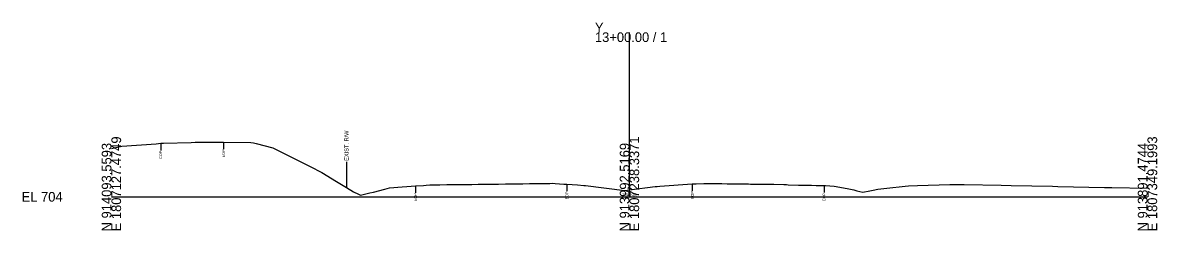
# Model space of a CAD drawing. Extents: x -26 to 3303, y -30 to 9580.
# Drawn here: x -25.7 to 302.8, y 2990.3 to 3050.4 of the extents above; entities that cross this region are included whole.
import ezdxf

# ---------------------------------------------------------------- set-up
doc = ezdxf.new("R2010")
doc.units = 0
for name, color, linetype in [('Exist Cross Section Cell', 7, 'Continuous'), ('Exist XS Center Line Elevation Label', 7, 'Continuous'), ('Exist XS Ground Line', 7, 'Continuous'), ('Old_Level_10', 7, 'Continuous')]:
    doc.layers.add(name, color=color, linetype=linetype)

msp = doc.modelspace()

# ---------------------------------------------------------------- linework, layer by layer
at = {"layer": 'Exist Cross Section Cell'}
for p, q in [((150, 3000), (150, 3047.62)), ((0, 3000), (150, 3000)), ((150, 3000), (300, 3000))]:
    msp.add_line(p, q, dxfattribs=at)
at = {"layer": 'Exist XS Ground Line'}
msp.add_lwpolyline([(0, 3014.04), (3.05, 3014.62), (12.99, 3015.39), (14.27, 3015.49), (15.12, 3015.51), (23.12, 3015.76), (24.2, 3015.78), (32.47, 3015.87), (40.37, 3015.69), (41.11, 3015.68), (41.91, 3015.45), (46.78, 3014.23), (49.82, 3012.67), (57.54, 3008.76), (60.94, 3007.01), (65.15, 3004.43), (67.15, 3003.27), (68.03, 3002.73), (70.1, 3001.42), (71.54, 3000.78), (72.15, 3000.52), (74.81, 3001.14), (75.85, 3001.38), (79.18, 3002.26), (80.5, 3002.57), (84.2, 3002.92), (85.56, 3003.03), (88.05, 3003.23), (90.38, 3003.31), (91.09, 3003.36), (92.23, 3003.46), (93.75, 3003.48), (95.1, 3003.5), (97.13, 3003.53), (98.77, 3003.55), (99.68, 3003.56), (100.52, 3003.57), (101.45, 3003.57), (102.48, 3003.58), (103.53, 3003.58), (104.34, 3003.59), (106.19, 3003.62), (106.76, 3003.62), (107.28, 3003.63), (109.89, 3003.67), (110.29, 3003.68), (110.67, 3003.68), (112.07, 3003.69), (114.13, 3003.72), (115.83, 3003.75), (117.42, 3003.78), (119.15, 3003.8), (121.04, 3003.83), (122.68, 3003.84), (124.7, 3003.87), (126.23, 3003.88), (126.92, 3003.89), (127.62, 3003.91), (128.49, 3003.85), (129.77, 3003.75), (130.96, 3003.71), (131.87, 3003.69), (134.94, 3003.44), (136.74, 3003.3), (137.24, 3003.26), (148.65, 3001.8), (150, 3001.98), (157.49, 3002.99), (158.02, 3003.03), (158.76, 3003.08), (168.2, 3003.78), (168.51, 3003.79), (169.31, 3003.78), (171.56, 3003.84), (172.33, 3003.89), (174.03, 3003.86), (174.94, 3003.85), (175.78, 3003.84), (176.7, 3003.83), (178.33, 3003.81), (179.31, 3003.8), (180.4, 3003.79), (181.69, 3003.77), (183.5, 3003.74), (184.07, 3003.74), (184.5, 3003.72), (185.06, 3003.71), (186.36, 3003.69), (187.85, 3003.67), (188.43, 3003.67), (189.92, 3003.65), (191.84, 3003.62), (194.74, 3003.57), (195.45, 3003.55), (195.91, 3003.52), (198.94, 3003.42), (200.55, 3003.38), (201.98, 3003.35), (202.32, 3003.34), (202.69, 3003.33), (204.1, 3003.3), (205.39, 3003.26), (206.02, 3003.25), (206.34, 3003.26), (206.75, 3003.24), (209.26, 3003.07), (212.99, 3002.41), (214.95, 3002.03), (215.88, 3001.78), (217.61, 3001.32), (219.6, 3001.72), (220.57, 3001.93), (221.94, 3002.18), (224.51, 3002.46), (229.87, 3003.09), (230.82, 3003.2), (233.43, 3003.32), (242.81, 3003.59), (246.96, 3003.6), (257.65, 3003.39), (260.49, 3003.29), (272.5, 3003.05), (274.02, 3003.03), (287.55, 3002.68), (289.71, 3002.66), (300, 3002.55)], dxfattribs=at)
at = {"layer": 'Old_Level_10'}
for p, q in [((14.27, 3015.49), (14.27, 3013.44)), ((32.47, 3015.87), (32.47, 3013.82)), ((68.06, 3010.11), (68.06, 3002.71)), ((88.05, 3003.23), (88.05, 3001.18)), ((131.87, 3003.69), (131.87, 3001.64)), ((168.2, 3003.78), (168.2, 3001.73)), ((206.34, 3003.26), (206.34, 3001.21))]:
    msp.add_line(p, q, dxfattribs=at)

# ---------------------------------------------------------------- texts
at = {"layer": 'Exist Cross Section Cell'}
for s, p in [('Y', (140, 3047.62)), ('13+00.00 / 1', (140, 3044.82)), ('EL 704', (-26, 2998.6))]:
    msp.add_text(s, height=2.8, dxfattribs=at).set_placement(p)
for s, p in [('E 1807127.4749', (2.8, 2990)), ('E 1807238.3371', (152.8, 2990)), ('E 1807349.1993', (302.8, 2990)), ('N 914093.5593', (0, 2990)), ('N 913992.5169', (150, 2990)), ('N 913891.4744', (300, 2990))]:
    msp.add_text(s, height=2.8, rotation=90, dxfattribs=at).set_placement(p)
at = {"layer": 'Exist XS Center Line Elevation Label'}
msp.add_text('705.98', height=1, dxfattribs=at).set_placement((147.86, 2999.98))
at = {"layer": 'Old_Level_10'}
for s, height, p in [('EXIST. R/W', 1.181, (68.65, 3010.41)), ('EOP', 0.787, (14.66, 3011.04)), ('EOP', 0.787, (32.86, 3011.42)), ('EOP', 0.787, (88.45, 2998.79)), ('EOP', 0.787, (132.26, 2999.24)), ('EOP', 0.787, (168.6, 2999.33)), ('EOP', 0.787, (206.73, 2998.81))]:
    msp.add_text(s, height=height, rotation=90, dxfattribs=at).set_placement(p)

doc.saveas('drawing.dxf')
